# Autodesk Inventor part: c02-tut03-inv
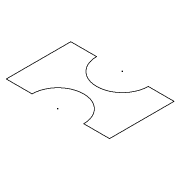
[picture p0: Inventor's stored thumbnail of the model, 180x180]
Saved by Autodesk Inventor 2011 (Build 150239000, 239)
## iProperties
Created: 2009-04
Part Number: c02-tut03-inv
Document SubType Name: Modeling
Designer: Sham
Density: 1 g/cm^3
Author: Sham
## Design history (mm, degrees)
sketch "Sketch1"
  geometry: L1 (-12, 15)-(-24, 15); L2 (-24, 15)-(-24, -15); L3 (-24, -15)-(-12, -15); L4 (12, -15)-(24, -15); L5 (24, -15)-(24, 15); L6 (24, 15)-(12, 15); A1 r 12 centre (0, 15) between (-12, 15) and (12, 15); A2 r 12 centre (0, -15) between (12, -15) and (-12, -15)
  constraints: 12 end point, 4 point on circle, 2 centre point, 1 other
